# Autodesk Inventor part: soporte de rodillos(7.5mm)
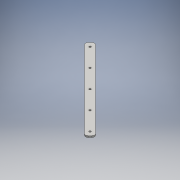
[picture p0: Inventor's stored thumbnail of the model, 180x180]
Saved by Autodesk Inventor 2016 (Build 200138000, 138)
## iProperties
Created: 2016-06
Part Number: soporte de rodillos(7.5mm)
Material: Genérico
Document SubType Name: Modeling
Designer: adm
Density: 1 g/cm^3
Appearance: Valor por defecto
Author: adm
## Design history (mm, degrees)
sketch "Boceto1"
  geometry: L1 (144.957, -166.17)-(166.17, -144.957); L2 (166.17, -187.383)-(196.17, -187.383); L3 (166.17, -144.957)-(-144.957, 166.17); L4 (-166.17, 144.957)-(144.957, -166.17); L5 (166.17, -187.383)-(-166.17, 187.383); L6 (187.383, -166.17)-(-187.383, 166.17); L7 (-166.17, 144.957)-(-144.957, 166.17); C1 r 3.75 at (70.711, -70.711); C2 r 3.75 at (141.421, -141.421); C3 r 3.75 at (0, 0); C4 r 3.75 at (-70.711, 70.711); C5 r 3.75 at (-141.421, 141.421); 7 further points
  constraints: 14 end point, 5 centre point, 5 coincident, 2 midpoint, 1 horizontal, 1 parallel
  dimensions: "d0" = 500 distance of L5.end L6.start; "d1" = 7.5 diameter of C5; "d2" = 7.5 diameter of C4; "d3" = 7.5 diameter of C3; "d4" = 7.5 diameter of C1; "d5" = 7.5 diameter of C2
extrude "Extrusión1" new body sketch "Boceto1" distance "d6" = 6; taper "d7" = 0 deg
fillet "Empalme1" dims "d8" = 10
node "Sólido1"
